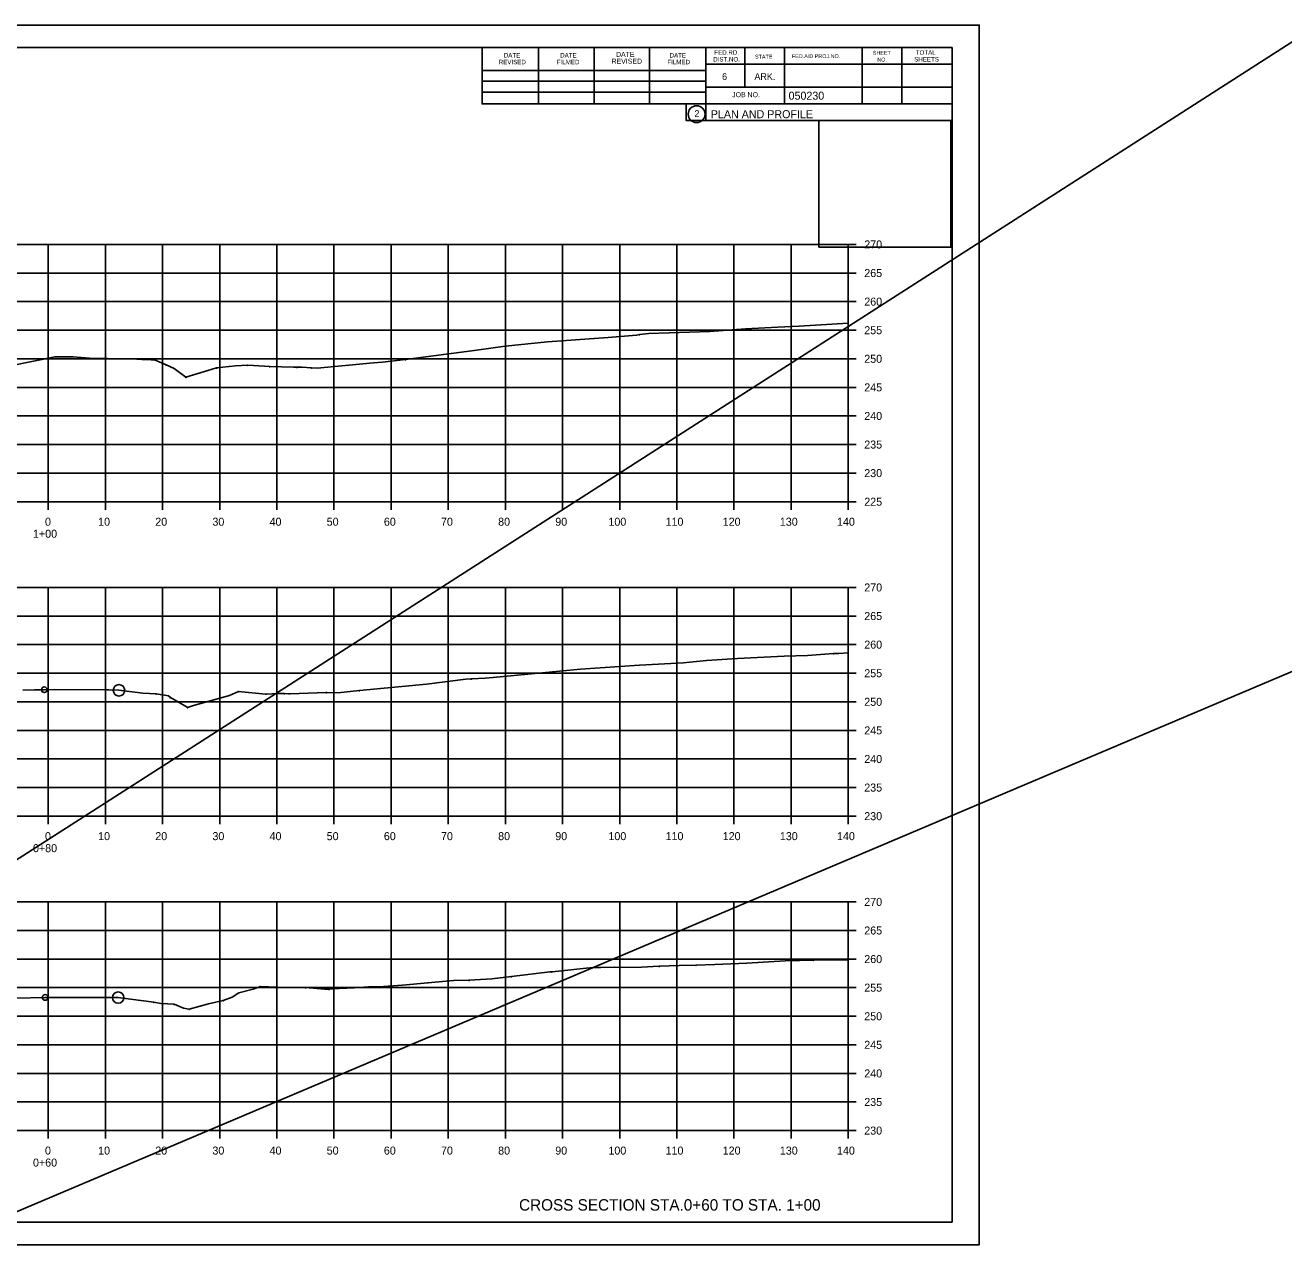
# Model space of a CAD drawing. Extents: x 1300404 to 1323571, y 234004 to 252077.
# Drawn here: x 1315713.2 to 1315933.5, y 240208.4 to 240421.8 of the extents above; entities that cross this region are included whole.
import ezdxf

# ---------------------------------------------------------------- set-up
doc = ezdxf.new("R2010")
doc.units = 0
for name, color, linetype in [('Default', 7, 'Continuous'), ('R_Axis', 7, 'Continuous'), ('R_Axis Annot', 7, 'Continuous'), ('R_Border', 7, 'Continuous'), ('R_Border Prem', 7, 'Continuous'), ('R_Draft', 7, 'Continuous'), ('R_Exist Surface', 7, 'Continuous'), ('R_Floodway', 7, 'Continuous'), ('R_Flooplain', 7, 'Continuous'), ('R_Grid', 7, 'Continuous'), ('R_No Plot', 7, 'Continuous')]:
    doc.layers.add(name, color=color, linetype=linetype)

msp = doc.modelspace()

# ---------------------------------------------------------------- linework, layer by layer
at = {"layer": 'Default'}
for p, q in [((1315559.28, 240417.86), (1315875.46, 240417.86)), ((1315793.2, 240407.98), (1315793.2, 240417.86)), ((1315803.06, 240407.98), (1315803.06, 240417.66)), ((1315812.82, 240407.98), (1315812.82, 240417.66)), ((1315822.5, 240407.98), (1315822.5, 240417.66)), ((1315832.36, 240417.86), (1315832.36, 240405.06)), ((1315839.2, 240417.86), (1315839.2, 240410.92)), ((1315846.14, 240417.86), (1315846.14, 240407.98)), ((1315859.72, 240417.86), (1315859.72, 240407.98)), ((1315866.66, 240417.86), (1315866.66, 240407.98)), ((1315875.46, 240212.4), (1315875.46, 240417.86)), ((1315875.46, 240414.92), (1315832.36, 240414.92)), ((1315875.46, 240414.94), (1315875.46, 240414.94)), ((1315793.2, 240413.84), (1315832.36, 240413.84)), ((1315793.2, 240411.98), (1315832.36, 240411.98)), ((1315875.46, 240410.92), (1315832.36, 240410.92)), ((1315835.32, 240410.92), (1315875.46, 240410.92)), ((1315793.2, 240407.98), (1315793.2, 240410.04)), ((1315793.2, 240410.04), (1315832.36, 240410.04)), ((1315875.46, 240407.98), (1315793.2, 240407.98)), ((1315832.36, 240405.06), (1315875.46, 240405.06)), ((1315875.46, 240212.4), (1315559.28, 240212.4))]:
    msp.add_line(p, q, dxfattribs=at)
msp.add_circle((1315830.74, 240406.2), 1.47, dxfattribs=at)
at = {"layer": 'R_Axis'}
for p, q in [((1315857.28, 240338.4), (1315857.28, 240383.4)), ((1315858.68, 240383.4), (1315857.28, 240383.4)), ((1315858.68, 240378.4), (1315857.28, 240378.4)), ((1315858.68, 240373.4), (1315857.28, 240373.4)), ((1315858.68, 240368.4), (1315857.28, 240368.4)), ((1315858.68, 240363.4), (1315857.28, 240363.4)), ((1315858.68, 240358.4), (1315857.28, 240358.4)), ((1315858.68, 240353.4), (1315857.28, 240353.4)), ((1315858.68, 240348.4), (1315857.28, 240348.4)), ((1315858.68, 240343.4), (1315857.28, 240343.4)), ((1315577.28, 240338.4), (1315857.28, 240338.4)), ((1315717.28, 240337), (1315717.28, 240338.4)), ((1315727.28, 240337), (1315727.28, 240338.4)), ((1315737.28, 240337), (1315737.28, 240338.4)), ((1315747.28, 240337), (1315747.28, 240338.4)), ((1315757.28, 240337), (1315757.28, 240338.4)), ((1315767.28, 240337), (1315767.28, 240338.4)), ((1315777.28, 240337), (1315777.28, 240338.4)), ((1315787.28, 240337), (1315787.28, 240338.4)), ((1315797.28, 240337), (1315797.28, 240338.4)), ((1315807.28, 240337), (1315807.28, 240338.4)), ((1315817.28, 240337), (1315817.28, 240338.4)), ((1315827.28, 240337), (1315827.28, 240338.4)), ((1315837.28, 240337), (1315837.28, 240338.4)), ((1315847.28, 240337), (1315847.28, 240338.4)), ((1315857.28, 240337), (1315857.28, 240338.4)), ((1315858.68, 240338.4), (1315857.28, 240338.4)), ((1315857.28, 240283.4), (1315857.28, 240323.4)), ((1315858.68, 240323.4), (1315857.28, 240323.4)), ((1315858.68, 240318.4), (1315857.28, 240318.4)), ((1315858.68, 240313.4), (1315857.28, 240313.4)), ((1315858.68, 240308.4), (1315857.28, 240308.4)), ((1315858.68, 240303.4), (1315857.28, 240303.4)), ((1315858.68, 240298.4), (1315857.28, 240298.4)), ((1315858.68, 240293.4), (1315857.28, 240293.4)), ((1315858.68, 240288.4), (1315857.28, 240288.4)), ((1315577.28, 240283.4), (1315857.28, 240283.4)), ((1315717.28, 240282), (1315717.28, 240283.4)), ((1315727.28, 240282), (1315727.28, 240283.4)), ((1315737.28, 240282), (1315737.28, 240283.4)), ((1315747.28, 240282), (1315747.28, 240283.4)), ((1315757.28, 240282), (1315757.28, 240283.4)), ((1315767.28, 240282), (1315767.28, 240283.4)), ((1315777.28, 240282), (1315777.28, 240283.4)), ((1315787.28, 240282), (1315787.28, 240283.4)), ((1315797.28, 240282), (1315797.28, 240283.4)), ((1315807.28, 240282), (1315807.28, 240283.4)), ((1315817.28, 240282), (1315817.28, 240283.4)), ((1315827.28, 240282), (1315827.28, 240283.4)), ((1315837.28, 240282), (1315837.28, 240283.4)), ((1315847.28, 240282), (1315847.28, 240283.4)), ((1315857.28, 240282), (1315857.28, 240283.4)), ((1315858.68, 240283.4), (1315857.28, 240283.4)), ((1315857.28, 240228.4), (1315857.28, 240268.4)), ((1315858.68, 240268.4), (1315857.28, 240268.4)), ((1315858.68, 240263.4), (1315857.28, 240263.4)), ((1315858.68, 240258.4), (1315857.28, 240258.4)), ((1315858.68, 240253.4), (1315857.28, 240253.4)), ((1315858.68, 240248.4), (1315857.28, 240248.4)), ((1315858.68, 240243.4), (1315857.28, 240243.4)), ((1315858.68, 240238.4), (1315857.28, 240238.4)), ((1315858.68, 240233.4), (1315857.28, 240233.4)), ((1315577.28, 240228.4), (1315857.28, 240228.4)), ((1315717.28, 240227), (1315717.28, 240228.4)), ((1315727.28, 240227), (1315727.28, 240228.4)), ((1315737.28, 240227), (1315737.28, 240228.4)), ((1315747.28, 240227), (1315747.28, 240228.4)), ((1315757.28, 240227), (1315757.28, 240228.4)), ((1315767.28, 240227), (1315767.28, 240228.4)), ((1315777.28, 240227), (1315777.28, 240228.4)), ((1315787.28, 240227), (1315787.28, 240228.4)), ((1315797.28, 240227), (1315797.28, 240228.4)), ((1315807.28, 240227), (1315807.28, 240228.4)), ((1315817.28, 240227), (1315817.28, 240228.4)), ((1315827.28, 240227), (1315827.28, 240228.4)), ((1315837.28, 240227), (1315837.28, 240228.4)), ((1315847.28, 240227), (1315847.28, 240228.4)), ((1315857.28, 240227), (1315857.28, 240228.4)), ((1315858.68, 240228.4), (1315857.28, 240228.4))]:
    msp.add_line(p, q, dxfattribs=at)
at = {"layer": 'R_Draft'}
for points in [[(1315839.29, 240368.67), (1315839.34, 240368.57), (1315839.24, 240368.57)], [(1315820.72, 240367.69), (1315820.77, 240367.59), (1315820.67, 240367.59)], [(1315797.22, 240365.68), (1315797.27, 240365.58), (1315797.17, 240365.58)], [(1315737.93, 240362.37), (1315737.98, 240362.27), (1315737.88, 240362.27)], [(1315746.75, 240361.86), (1315746.8, 240361.76), (1315746.7, 240361.76)], [(1315752.18, 240362.34), (1315752.23, 240362.24), (1315752.13, 240362.24)], [(1315756.01, 240362.12), (1315756.06, 240362.02), (1315755.96, 240362.02)], [(1315760.81, 240361.97), (1315760.86, 240361.87), (1315760.76, 240361.87)], [(1315763.29, 240361.87), (1315763.34, 240361.77), (1315763.24, 240361.77)], [(1315779.8, 240363.31), (1315779.85, 240363.21), (1315779.75, 240363.21)], [(1315741.37, 240360.22), (1315741.42, 240360.12), (1315741.32, 240360.12)], [(1315854.69, 240311.88), (1315854.74, 240311.78), (1315854.64, 240311.78)], [(1315791.33, 240307.46), (1315791.38, 240307.36), (1315791.28, 240307.36)], [(1315736.16, 240304.82), (1315736.21, 240304.72), (1315736.11, 240304.72)], [(1315750.58, 240305.26), (1315750.63, 240305.16), (1315750.53, 240305.16)], [(1315755.45, 240304.81), (1315755.5, 240304.71), (1315755.4, 240304.71)], [(1315758.58, 240304.89), (1315758.63, 240304.79), (1315758.53, 240304.79)], [(1315765.92, 240305.08), (1315765.97, 240304.98), (1315765.87, 240304.98)], [(1315771.75, 240305.42), (1315771.8, 240305.32), (1315771.7, 240305.32)], [(1315738.66, 240304.18), (1315738.71, 240304.08), (1315738.61, 240304.08)], [(1315741.65, 240302.45), (1315741.7, 240302.35), (1315741.6, 240302.35)], [(1315851.23, 240258.27), (1315851.28, 240258.17), (1315851.18, 240258.17)], [(1315805.4, 240256.23), (1315805.45, 240256.13), (1315805.35, 240256.13)], [(1315824.21, 240257.2), (1315824.26, 240257.1), (1315824.16, 240257.1)], [(1315830.63, 240257.4), (1315830.68, 240257.3), (1315830.58, 240257.3)], [(1315783.68, 240254.32), (1315783.73, 240254.22), (1315783.63, 240254.22)], [(1315790.93, 240254.75), (1315790.98, 240254.65), (1315790.88, 240254.65)], [(1315798.32, 240255.39), (1315798.37, 240255.29), (1315798.27, 240255.29)], [(1315750.66, 240252.57), (1315750.71, 240252.47), (1315750.61, 240252.47)], [(1315754.4, 240253.65), (1315754.45, 240253.55), (1315754.35, 240253.55)], [(1315762.31, 240253.46), (1315762.36, 240253.36), (1315762.26, 240253.36)], [(1315766.39, 240253.16), (1315766.44, 240253.06), (1315766.34, 240253.06)], [(1315735.76, 240250.89), (1315735.81, 240250.79), (1315735.71, 240250.79)], [(1315739.29, 240250.55), (1315739.34, 240250.45), (1315739.24, 240250.45)], [(1315741.94, 240249.68), (1315741.99, 240249.58), (1315741.89, 240249.58)], [(1315747.9, 240251.21), (1315747.95, 240251.11), (1315747.85, 240251.11)]]:
    msp.add_lwpolyline(points, close=True, dxfattribs=at)
at = {"layer": 'R_Exist Surface'}
for points in [[(1315702.58, 240360.52), (1315718.41, 240363.74), (1315719.59, 240363.77), (1315721.64, 240363.74), (1315724.49, 240363.49), (1315724.83, 240363.48), (1315726.77, 240363.46), (1315727.37, 240363.45), (1315727.64, 240363.45), (1315729.55, 240363.42), (1315730.93, 240363.4), (1315731.24, 240363.4), (1315731.9, 240363.39), (1315733.66, 240363.3), (1315734.12, 240363.28), (1315734.34, 240363.27), (1315735.27, 240363.24), (1315735.87, 240363.2), (1315737.93, 240362.32), (1315739.31, 240361.69), (1315741.37, 240360.17), (1315745.23, 240361.36), (1315746.75, 240361.81), (1315750.04, 240362.17), (1315752.18, 240362.29), (1315755.12, 240362.1), (1315756.01, 240362.07), (1315760.2, 240361.91), (1315760.81, 240361.92), (1315761.18, 240361.91), (1315761.7, 240361.92), (1315763.29, 240361.82), (1315764.33, 240361.78), (1315774.17, 240362.67), (1315775.78, 240362.81), (1315779.8, 240363.26), (1315791.82, 240364.88), (1315797.22, 240365.63), (1315804.65, 240366.38), (1315815.26, 240367.11), (1315820.24, 240367.53), (1315820.72, 240367.64), (1315822.36, 240367.84), (1315833.06, 240368.19), (1315839.29, 240368.62), (1315842.66, 240368.83), (1315844.98, 240368.95), (1315848.68, 240369.13), (1315857.28, 240369.66)], [(1315712.85, 240305.44), (1315714.85, 240305.52), (1315716.59, 240305.52), (1315718.37, 240305.54), (1315727.56, 240305.47), (1315727.8, 240305.47), (1315727.91, 240305.47), (1315729.66, 240305.41), (1315733.83, 240304.89), (1315736.16, 240304.77), (1315738.35, 240304.44), (1315738.66, 240304.13), (1315741.59, 240302.45), (1315741.65, 240302.4), (1315742.71, 240302.73), (1315748.97, 240304.5), (1315750.58, 240305.21), (1315755.31, 240304.75), (1315755.34, 240304.75), (1315755.37, 240304.75), (1315755.45, 240304.76), (1315757.44, 240304.88), (1315758.58, 240304.84), (1315759.32, 240304.82), (1315759.59, 240304.82), (1315765.92, 240305.03), (1315766.07, 240305.02), (1315767.97, 240304.95), (1315771.75, 240305.37), (1315783.46, 240306.51), (1315790.37, 240307.35), (1315791.33, 240307.41), (1315793.74, 240307.51), (1315795.11, 240307.68), (1315798.16, 240307.94), (1315810.4, 240309.09), (1315820.73, 240309.81), (1315828.45, 240310.24), (1315829.55, 240310.36), (1315832.5, 240310.63), (1315837.87, 240310.98), (1315846.08, 240311.4), (1315850.13, 240311.52), (1315854.69, 240311.83), (1315855.44, 240311.85), (1315855.58, 240311.86), (1315857.28, 240311.94)], [(1315711.57, 240251.59), (1315716.75, 240251.7), (1315724.95, 240251.69), (1315729.51, 240251.66), (1315731.65, 240251.39), (1315735.76, 240250.84), (1315736.99, 240250.65), (1315739.29, 240250.5), (1315740.95, 240249.83), (1315741.94, 240249.63), (1315745.32, 240250.56), (1315747.9, 240251.16), (1315749.45, 240251.75), (1315750.66, 240252.52), (1315753.15, 240253.15), (1315754.4, 240253.6), (1315758.61, 240253.43), (1315762.31, 240253.41), (1315765.61, 240253.16), (1315766.39, 240253.11), (1315768.2, 240253.24), (1315770.88, 240253.39), (1315773.31, 240253.52), (1315775.14, 240253.57), (1315779.26, 240253.81), (1315783.68, 240254.27), (1315788.2, 240254.64), (1315790.93, 240254.7), (1315794.91, 240254.96), (1315798.32, 240255.34), (1315805.07, 240256.15), (1315805.4, 240256.18), (1315806.55, 240256.3), (1315811.42, 240256.8), (1315812.63, 240256.94), (1315813.98, 240256.92), (1315816.42, 240256.99), (1315817.42, 240256.95), (1315821.07, 240257.01), (1315824.21, 240257.15), (1315827.66, 240257.27), (1315830.63, 240257.35), (1315833.94, 240257.43), (1315839.51, 240257.71), (1315846.24, 240258.07), (1315851.23, 240258.22), (1315857.28, 240258.27)]]:
    msp.add_lwpolyline(points, dxfattribs=at)
at = {"layer": 'R_Floodway'}
msp.add_lwpolyline([(1316837.8, 240552.77), (1316620.61, 240466.93), (1316398.83, 240386.16), (1316131.18, 240356.09), (1315994.58, 240333.94), (1315688.1, 240204.21), (1315576.62, 240103.36), (1315282.23, 239827.84), (1314935.72, 239477.52)], dxfattribs=at)
at = {"layer": 'R_Flooplain'}
msp.add_line((1315692.25, 240263.28), (1316007.17, 240465.17), dxfattribs=at)
at = {"layer": 'R_Grid'}
for p, q in [((1315577.28, 240383.4), (1315857.28, 240383.4)), ((1315717.28, 240338.4), (1315717.28, 240383.4)), ((1315727.28, 240338.4), (1315727.28, 240383.4)), ((1315737.28, 240338.4), (1315737.28, 240383.4)), ((1315747.28, 240338.4), (1315747.28, 240383.4)), ((1315757.28, 240338.4), (1315757.28, 240383.4)), ((1315767.28, 240338.4), (1315767.28, 240383.4)), ((1315777.28, 240338.4), (1315777.28, 240383.4)), ((1315787.28, 240338.4), (1315787.28, 240383.4)), ((1315797.28, 240338.4), (1315797.28, 240383.4)), ((1315807.28, 240338.4), (1315807.28, 240383.4)), ((1315817.28, 240338.4), (1315817.28, 240383.4)), ((1315827.28, 240338.4), (1315827.28, 240383.4)), ((1315837.28, 240338.4), (1315837.28, 240383.4)), ((1315847.28, 240338.4), (1315847.28, 240383.4)), ((1315857.28, 240338.4), (1315857.28, 240383.4)), ((1315577.28, 240378.4), (1315857.28, 240378.4)), ((1315577.28, 240373.4), (1315857.28, 240373.4)), ((1315577.28, 240368.4), (1315857.28, 240368.4)), ((1315577.28, 240363.4), (1315857.28, 240363.4)), ((1315577.28, 240358.4), (1315857.28, 240358.4)), ((1315577.28, 240353.4), (1315857.28, 240353.4)), ((1315577.28, 240348.4), (1315857.28, 240348.4)), ((1315577.28, 240343.4), (1315857.28, 240343.4)), ((1315577.28, 240338.4), (1315857.28, 240338.4)), ((1315577.28, 240323.4), (1315857.28, 240323.4)), ((1315717.28, 240283.4), (1315717.28, 240323.4)), ((1315727.28, 240283.4), (1315727.28, 240323.4)), ((1315737.28, 240283.4), (1315737.28, 240323.4)), ((1315747.28, 240283.4), (1315747.28, 240323.4)), ((1315757.28, 240283.4), (1315757.28, 240323.4)), ((1315767.28, 240283.4), (1315767.28, 240323.4)), ((1315777.28, 240283.4), (1315777.28, 240323.4)), ((1315787.28, 240283.4), (1315787.28, 240323.4)), ((1315797.28, 240283.4), (1315797.28, 240323.4)), ((1315807.28, 240283.4), (1315807.28, 240323.4)), ((1315817.28, 240283.4), (1315817.28, 240323.4)), ((1315827.28, 240283.4), (1315827.28, 240323.4)), ((1315837.28, 240283.4), (1315837.28, 240323.4)), ((1315847.28, 240283.4), (1315847.28, 240323.4)), ((1315857.28, 240283.4), (1315857.28, 240323.4)), ((1315577.28, 240318.4), (1315857.28, 240318.4)), ((1315577.28, 240313.4), (1315857.28, 240313.4)), ((1315577.28, 240308.4), (1315857.28, 240308.4)), ((1315577.28, 240303.4), (1315857.28, 240303.4)), ((1315577.28, 240298.4), (1315857.28, 240298.4)), ((1315577.28, 240293.4), (1315857.28, 240293.4)), ((1315577.28, 240288.4), (1315857.28, 240288.4)), ((1315577.28, 240283.4), (1315857.28, 240283.4)), ((1315577.28, 240268.4), (1315857.28, 240268.4)), ((1315717.28, 240228.4), (1315717.28, 240268.4)), ((1315727.28, 240228.4), (1315727.28, 240268.4)), ((1315737.28, 240228.4), (1315737.28, 240268.4)), ((1315747.28, 240228.4), (1315747.28, 240268.4)), ((1315757.28, 240228.4), (1315757.28, 240268.4)), ((1315767.28, 240228.4), (1315767.28, 240268.4)), ((1315777.28, 240228.4), (1315777.28, 240268.4)), ((1315787.28, 240228.4), (1315787.28, 240268.4)), ((1315797.28, 240228.4), (1315797.28, 240268.4)), ((1315807.28, 240228.4), (1315807.28, 240268.4)), ((1315817.28, 240228.4), (1315817.28, 240268.4)), ((1315827.28, 240228.4), (1315827.28, 240268.4)), ((1315837.28, 240228.4), (1315837.28, 240268.4)), ((1315847.28, 240228.4), (1315847.28, 240268.4)), ((1315857.28, 240228.4), (1315857.28, 240268.4)), ((1315577.28, 240263.4), (1315857.28, 240263.4)), ((1315577.28, 240258.4), (1315857.28, 240258.4)), ((1315577.28, 240253.4), (1315857.28, 240253.4)), ((1315577.28, 240248.4), (1315857.28, 240248.4)), ((1315577.28, 240243.4), (1315857.28, 240243.4)), ((1315577.28, 240238.4), (1315857.28, 240238.4)), ((1315577.28, 240233.4), (1315857.28, 240233.4)), ((1315577.28, 240228.4), (1315857.28, 240228.4))]:
    msp.add_line(p, q, dxfattribs=at)
at = {"layer": 'R_No Plot'}
for p, q in [((1315546.87, 240421.76), (1315880.21, 240421.76)), ((1315546.87, 240208.42), (1315880.21, 240208.42))]:
    msp.add_line(p, q, dxfattribs=at)
for points in [[(1315546.87, 240421.76), (1315880.21, 240421.76), (1315880.21, 240208.42), (1315546.87, 240208.42)], [(1315793.2, 240417.86), (1315793.2, 240407.98), (1315828.93, 240407.98), (1315828.93, 240405.06), (1315852.13, 240405.06), (1315852.13, 240382.94), (1315875.46, 240382.94), (1315875.46, 240212.4), (1315559.28, 240212.4), (1315559.28, 240417.86)], [(1315852.13, 240405.09), (1315875.23, 240405.09), (1315875.23, 240382.94), (1315852.13, 240382.94)]]:
    msp.add_lwpolyline(points, close=True, dxfattribs=at)
for centre, radius in [((1315716.59, 240305.52), 0.5), ((1315729.66, 240305.41), 1), ((1315716.75, 240251.7), 0.5), ((1315729.51, 240251.66), 1)]:
    msp.add_circle(centre, radius, dxfattribs=at)

# ---------------------------------------------------------------- texts
at = {"layer": 'Default'}
msp.add_text('2', height=1.17, dxfattribs=at).set_placement((1315830.36, 240405.71))
at = {"layer": 'R_Axis Annot'}
for s, p in [('270', (1315860.08, 240382.7)), ('265', (1315860.08, 240377.7)), ('260', (1315860.08, 240372.7)), ('255', (1315860.08, 240367.7)), ('250', (1315860.08, 240362.7)), ('245', (1315860.08, 240357.7)), ('240', (1315860.08, 240352.7)), ('235', (1315860.08, 240347.7)), ('230', (1315860.08, 240342.7)), ('225', (1315860.08, 240337.7)), ('0', (1315716.71, 240334.2)), ('10', (1315726.01, 240334.2)), ('20', (1315736.01, 240334.2)), ('30', (1315746.01, 240334.2)), ('40', (1315756.01, 240334.2)), ('50', (1315766.01, 240334.2)), ('60', (1315776.01, 240334.2)), ('70', (1315786.01, 240334.2)), ('80', (1315796.01, 240334.2)), ('90', (1315806.01, 240334.2)), ('100', (1315815.31, 240334.2)), ('110', (1315825.31, 240334.2)), ('120', (1315835.31, 240334.2)), ('130', (1315845.31, 240334.2)), ('140', (1315855.31, 240334.2)), ('1+00', (1315714.61, 240332.1)), ('270', (1315860.08, 240322.7)), ('265', (1315860.08, 240317.7)), ('260', (1315860.08, 240312.7)), ('255', (1315860.08, 240307.7)), ('250', (1315860.08, 240302.7)), ('245', (1315860.08, 240297.7)), ('240', (1315860.08, 240292.7)), ('235', (1315860.08, 240287.7)), ('230', (1315860.08, 240282.7)), ('0', (1315716.71, 240279.2)), ('10', (1315726.01, 240279.2)), ('20', (1315736.01, 240279.2)), ('30', (1315746.01, 240279.2)), ('40', (1315756.01, 240279.2)), ('50', (1315766.01, 240279.2)), ('60', (1315776.01, 240279.2)), ('70', (1315786.01, 240279.2)), ('80', (1315796.01, 240279.2)), ('90', (1315806.01, 240279.2)), ('100', (1315815.31, 240279.2)), ('110', (1315825.31, 240279.2)), ('120', (1315835.31, 240279.2)), ('130', (1315845.31, 240279.2)), ('140', (1315855.31, 240279.2)), ('0+80', (1315714.61, 240277.1)), ('270', (1315860.08, 240267.7)), ('265', (1315860.08, 240262.7)), ('260', (1315860.08, 240257.7)), ('255', (1315860.08, 240252.7)), ('250', (1315860.08, 240247.7)), ('245', (1315860.08, 240242.7)), ('240', (1315860.08, 240237.7)), ('235', (1315860.08, 240232.7)), ('230', (1315860.08, 240227.7)), ('0', (1315716.71, 240224.2)), ('10', (1315726.01, 240224.2)), ('20', (1315736.01, 240224.2)), ('30', (1315746.01, 240224.2)), ('40', (1315756.01, 240224.2)), ('50', (1315766.01, 240224.2)), ('60', (1315776.01, 240224.2)), ('70', (1315786.01, 240224.2)), ('80', (1315796.01, 240224.2)), ('90', (1315806.01, 240224.2)), ('100', (1315815.31, 240224.2)), ('110', (1315825.31, 240224.2)), ('120', (1315835.31, 240224.2)), ('130', (1315845.31, 240224.2)), ('140', (1315855.31, 240224.2)), ('0+60', (1315714.61, 240222.1))]:
    msp.add_text(s, height=1.4, dxfattribs=at).set_placement(p)
at = {"layer": 'R_Border'}
for s, height, p in [('DATE', 0.782, (1315797, 240416.1)), ('DATE', 0.782, (1315806.86, 240416.1)), ('DATE', 0.879, (1315816.64, 240416.2)), ('DATE', 0.782, (1315826.02, 240416.1)), ('FED.RD.', 0.782, (1315833.84, 240416.58)), ('SHEET', 0.684, (1315861.58, 240416.58)), ('TOTAL', 0.782, (1315869.1, 240416.58)), ('REVISED', 0.782, (1315796.12, 240414.92)), ('FILMED', 0.782, (1315806.28, 240414.92)), ('REVISED', 0.879, (1315815.86, 240415.02)), ('FILMED', 0.782, (1315825.62, 240414.92)), ('DIST.NO.', 0.782, (1315833.64, 240415.4)), ('STATE', 0.684, (1315840.96, 240415.9)), ('FED.AID PROJ.NO.', 0.684, (1315847.42, 240416)), ('NO.', 0.684, (1315862.36, 240415.4)), ('SHEETS', 0.782, (1315868.82, 240415.4)), ('6', 1.17, (1315835.2, 240412.18)), ('ARK.', 1.172, (1315840.86, 240412.18)), ('JOB NO.', 0.879, (1315836.96, 240409.16))]:
    msp.add_text(s, height=height, dxfattribs=at).set_placement(p)
for s, p in [('050230', (1315846.83, 240408.72)), ('PLAN AND PROFILE', (1315833.22, 240405.49))]:
    msp.add_text(s, height=1.4, rotation=360, dxfattribs=at).set_placement(p)
at = {"layer": 'R_Border Prem'}
msp.add_text('DWB', height=0.01, dxfattribs=at).set_placement((1315836.15, 240399.37))
at = {"layer": 'R_Draft'}
msp.add_text('CROSS SECTION STA.0+60 TO STA. 1+00', height=2, dxfattribs=at).set_placement((1315799.67, 240214.4))

doc.saveas('drawing.dxf')
